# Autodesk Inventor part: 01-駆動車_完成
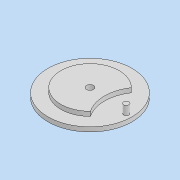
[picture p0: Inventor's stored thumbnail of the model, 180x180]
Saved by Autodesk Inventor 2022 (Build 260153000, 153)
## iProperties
Created: 2021-07
Part Number: 01-駆動車_完成
Material: 一般
Document SubType Name: Modeling
Designer: DesignLab
Density: 1 g/cm^3
Appearance: 既定
Author: DesignLab
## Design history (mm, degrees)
sketch "スケッチ1"
  geometry: C1 r 47.5 at (0, 0); 1 further point
  constraints: 1 centre point, 1 coincident
  dimensions: "d0" = 95 diameter of C1
extrude "押し出し1" new body sketch "スケッチ1" distance "d1" = 5; taper "d2" = 0 deg
sketch "スケッチ2"
  geometry: A1 r 33 centre (0, 0) between (23.541, 23.126) and (23.541, -23.126); A2 r 41.5 centre (58, 0) between (23.541, 23.126) and (23.541, -23.126); 1 further point
  constraints: 4 point on circle, 2 centre point, 1 coincident, 1 horizontal alignment
  dimensions: "d3" = 66 diameter of A1; "d4" = 41.5 radius of A2; "d5" = 58 distance of A2.centre point (0, 0)
extrude "押し出し2" join sketch "スケッチ2" distance "d6" = 5; taper "d7" = 0 deg
sketch "スケッチ3"
  geometry: C1 r 3 at (41, 0); 1 further point
  constraints: 1 centre point, 1 horizontal alignment
  dimensions: "d8" = 6 diameter of C1; "d9" = 41 distance of C1.centre point (0, 0)
extrude "押し出し3" join sketch "スケッチ3" distance "d10" = 10; taper "d11" = 0 deg
hole "穴1" diameter "d14" = 8; stored, may be unused: countersink angle "d18" = 90 deg, drill point angle "d20" = 118 deg; dims "d12" = 10, "d13" = 10, "d15" = 6, "d16" = 4, "d17" = 2, "d19" = 8
node "ソリッド1"
